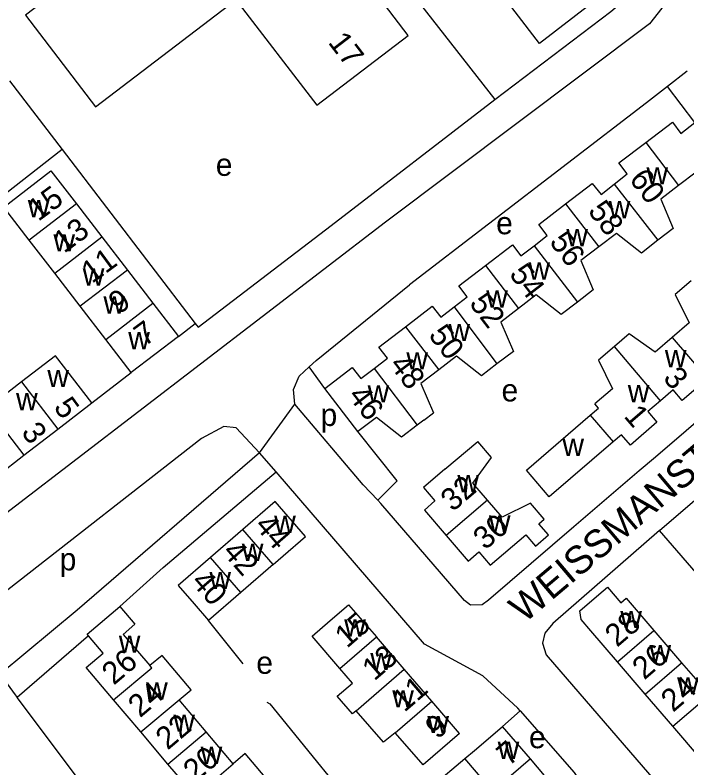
# Model space of a CAD drawing. Extents: x 158848 to 160613, y 385889 to 387762.
# Drawn here: x 160005.9 to 160125.8, y 386527.7 to 386662.2 of the extents above; entities that cross this region are included whole.
import ezdxf

# ---------------------------------------------------------------- set-up
doc = ezdxf.new("R2010")
doc.units = 0
for name, color, linetype in [('BLT_Basislijn', 7, 'Continuous'), ('BLT_Bebouwing', 7, 'Continuous'), ('BLT_Centroide', 7, 'Continuous'), ('BLT_Huisnummer', 7, 'Continuous'), ('BLT_Huisnummer_ tussenligend', 7, 'Continuous'), ('BLT_Onderverdeling_panden', 7, 'Continuous'), ('BLT_Straatnaam', 7, 'Continuous'), ('BLT_Vlakafsluiter', 7, 'Continuous')]:
    doc.layers.add(name, color=color, linetype=linetype)

msp = doc.modelspace()

# ---------------------------------------------------------------- linework, layer by layer
at = {"layer": 'BLT_Basislijn'}
for p, q in [((160125.84, 386652.14), (160122.33, 386649.41)), ((160004.85, 386650.41), (160014.24, 386638.14)), ((160127.21, 386642.98), (160122.33, 386649.41)), ((160062.28, 386624.59), (160091.49, 386647.08)), ((160014.24, 386638.14), (160038.02, 386607.09)), ((160035.02, 386604.77), (160038.02, 386607.09)), ((160019.55, 386592.89), (160026.6, 386598.34)), ((160061.18, 386595.45), (160058.37, 386599.34)), ((160000.42, 386578.15), (160007.45, 386583.53)), ((160052.45, 386580.6), (160049.48, 386583.96)), ((160117.29, 386580.74), (160105.63, 386570.74)), ((160156.76, 386528.66), (160120.89, 386570.12)), ((160024.56, 386556.5), (160032.3, 386563.48)), ((160046.58, 386546.31), (160040.39, 386554.01)), ((160018.99, 386551.28), (160006.23, 386540.3)), ((160018.93, 386523.43), (160006.23, 386540.3)), ((160096.06, 386537.88), (160092.88, 386535.1)), ((160070.18, 386515.95), (160086.18, 386529.36))]:
    msp.add_line(p, q, dxfattribs=at)
for points in [[(160037.07, 386716.89), (160066.71, 386678.86), (160091.49, 386647.08)], [(160091.49, 386647.08), (160112.23, 386662.8), (160114.67, 386664.97), (160111.18, 386670.16)], [(160121.03, 386668), (160121.35, 386667.04), (160121.3, 386663.42), (160119.12, 386660.61), (160072, 386625.2)], [(160122.33, 386649.41), (160118.57, 386646.49), (160076.28, 386613.96)], [(160014.24, 386638.14), (159973.45, 386606.21)], [(160072, 386625.2), (159994.85, 386566.02), (159992.27, 386564.83), (159988.99, 386564.97), (159986.32, 386567.3)], [(160038.02, 386607.09), (160038.55, 386606.41), (160062.28, 386624.59)], [(160058.37, 386599.34), (160059.6, 386600.47), (160076.28, 386613.96)], [(160153.03, 386611.43), (160120.17, 386583.21), (160117.29, 386580.74)], [(160055.81, 386592.66), (160055.54, 386595.28), (160056.56, 386597.68), (160058.37, 386599.34)], [(160070.62, 386575.53), (160068.02, 386578.28), (160055.81, 386592.66)], [(160049.48, 386583.96), (160045.31, 386588.46), (160043.15, 386588.7), (160039.17, 386586.55), (160004.57, 386559.51), (159997.74, 386553.78), (159997.8, 386551.51), (160003.17, 386544.41)], [(160070.62, 386575.53), (160074.05, 386578.99), (160067.05, 386587.78)], [(160120.89, 386570.12), (160138.05, 386584.8), (160139.23, 386585.32), (160141.71, 386585.23), (160143.94, 386583.68), (160176.56, 386545.83)], [(160049.48, 386583.96), (160016.93, 386555.88), (160003.17, 386544.41)], [(160032.3, 386563.48), (160052.45, 386580.6)], [(160096.06, 386537.88), (160095.64, 386538.36), (160089.38, 386544.17), (160078.95, 386549.8), (160052.45, 386580.6)], [(160105.63, 386570.74), (160090.41, 386557.64), (160089.25, 386556.84), (160087.15, 386556.77), (160086.07, 386557.61), (160071.18, 386574.93), (160070.62, 386575.53)], [(160120.89, 386570.12), (160101.88, 386553.46), (160100.45, 386551.77), (160100.03, 386549.96), (160100.67, 386547.91), (160133.83, 386509.51)], [(160003.17, 386544.41), (160005.89, 386540.76), (160006.23, 386540.3)], [(160050.78, 386539.46), (160051.37, 386539.12), (160070.18, 386515.95)], [(160096.06, 386537.88), (160105.65, 386526.85), (160106.06, 386526.36)]]:
    msp.add_lwpolyline(points, dxfattribs=at)
at = {"layer": 'BLT_Bebouwing'}
for p, q in [((160016.82, 386628.44), (160021.37, 386622.53)), ((160021.37, 386622.53), (160025.92, 386616.61)), ((160012.95, 386616.05), (160008.4, 386621.97)), ((160017.51, 386610.14), (160012.95, 386616.05)), ((160025.92, 386616.61), (160030.47, 386610.69)), ((160022.06, 386604.23), (160017.51, 386610.14)), ((160067.05, 386587.78), (160061.18, 386595.45)), ((160078.82, 386589.81), (160080.54, 386591.14)), ((160078.82, 386589.81), (160077.63, 386588.9)), ((160082.58, 386581.03), (160088.46, 386586)), ((160046.52, 386570.3), (160040.74, 386565.29)), ((160040.74, 386565.29), (160034.96, 386560.28)), ((160051.96, 386564.02), (160046.18, 386559.01)), ((160046.18, 386559.01), (160040.39, 386554.01)), ((160075.31, 386545.34), (160070.36, 386551.09)), ((160119.92, 386552.24), (160124.86, 386546.48)), ((160118.33, 386540.88), (160113.39, 386546.64)), ((160124.86, 386546.48), (160129.79, 386540.73)), ((160080.26, 386539.59), (160075.31, 386545.34)), ((160123.27, 386535.13), (160118.33, 386540.88)), ((160028.29, 386534.14), (160023.42, 386539.88)), ((160039.95, 386534.15), (160035.13, 386539.83)), ((160085.2, 386533.84), (160080.26, 386539.59)), ((160097.86, 386529.29), (160092.88, 386535.1)), ((160128.21, 386529.38), (160123.27, 386535.13)), ((160033.16, 386528.39), (160028.29, 386534.14)), ((160044.82, 386528.4), (160039.95, 386534.15)), ((160086.18, 386529.36), (160087.89, 386530.83)), ((160038.03, 386522.65), (160033.16, 386528.39)), ((160091.15, 386523.55), (160086.18, 386529.36)), ((160102.84, 386523.47), (160097.86, 386529.29))]:
    msp.add_line(p, q, dxfattribs=at)
msp.add_lwpolyline([(160039.46, 386707.71), (160023, 386695.11), (160033.29, 386681.66), (160007.73, 386662.12), (160020.21, 386645.77), (160045.27, 386664.94), (160059.74, 386646.07), (160076.07, 386658.53), (160059.12, 386680.71), (160058.39, 386680.18), (160051.48, 386689.22), (160052.83, 386690.21)], close=True, dxfattribs=at)
for points in [[(160096.96, 386679.71), (160108.81, 386664.29), (160099.47, 386657.11), (160087.64, 386672.57)], [(160118.45, 386639.4), (160123.23, 386643.05), (160124.74, 386640.99), (160127.21, 386642.98)], [(160112.82, 386631.95), (160115.16, 386633.78), (160113.68, 386635.74), (160118.45, 386639.4)], [(160008.4, 386621.97), (160003.86, 386627.86), (160012.27, 386634.36), (160016.82, 386628.44)], [(160134.93, 386632.93), (160131.93, 386630.62), (160127.48, 386634.13), (160124.33, 386631.72)], [(160104.15, 386628.44), (160108.92, 386632.1), (160110.47, 386630.11), (160112.82, 386631.95)], [(160124.33, 386631.72), (160121.15, 386629.27), (160123.37, 386624.04), (160120.64, 386621.94)], [(160098.51, 386620.96), (160100.88, 386622.78), (160099.39, 386624.78), (160104.15, 386628.44)], [(160120.64, 386621.94), (160117.67, 386619.66), (160113.21, 386623.17), (160110.06, 386620.75)], [(160089.87, 386617.46), (160094.65, 386621.11), (160096.14, 386619.13), (160098.51, 386620.96)], [(160110.06, 386620.75), (160106.87, 386618.3), (160109.09, 386613.07), (160106.26, 386610.9)], [(160084.23, 386610.02), (160086.58, 386611.83), (160085.08, 386613.8), (160089.87, 386617.46)], [(160126.54, 386614.69), (160123.71, 386612.25), (160126.23, 386607.17), (160123.18, 386604.56)], [(160106.26, 386610.9), (160103.38, 386608.68), (160098.92, 386612.19), (160095.75, 386609.76)], [(160030.47, 386610.69), (160035.02, 386604.77)], [(160075.58, 386606.49), (160080.34, 386610.15), (160081.88, 386608.21), (160084.23, 386610.02)], [(160095.75, 386609.76), (160092.58, 386607.32), (160094.82, 386602.1), (160091.89, 386599.85)], [(160069.95, 386599.05), (160072.33, 386600.85), (160070.82, 386602.84), (160075.58, 386606.49)], [(160035.02, 386604.77), (160026.6, 386598.34)], [(160123.18, 386604.56), (160120.14, 386601.95), (160115.49, 386605.21), (160112.85, 386602.94)], [(160026.6, 386598.34), (160022.06, 386604.23)], [(160112.85, 386602.94), (160110.04, 386600.53), (160112.55, 386595.43), (160109.39, 386592.71)], [(160019.55, 386592.89), (160013.05, 386601.32), (160007, 386596.63)], [(160091.89, 386599.85), (160089.11, 386597.72), (160084.65, 386601.23), (160081.49, 386598.8)], [(160061.18, 386595.45), (160066.06, 386599.2), (160067.57, 386597.25), (160069.95, 386599.05)], [(160081.49, 386598.8), (160078.3, 386596.35), (160080.54, 386591.14)], [(160129.49, 386597.2), (160124.98, 386593.32), (160123.38, 386595.22), (160121.11, 386593.27)], [(160007, 386596.63), (160000.95, 386591.95), (160007.45, 386583.53)], [(160013.5, 386588.21), (160019.55, 386592.89)], [(160108.55, 386590.67), (160110.05, 386591.96), (160109.39, 386592.71)], [(160121.11, 386593.27), (160118.84, 386591.33), (160120.43, 386589.42), (160115.72, 386585.36), (160114.13, 386587.21), (160112.63, 386585.92)], [(160077.63, 386588.9), (160074.85, 386586.76), (160070.39, 386590.27), (160067.05, 386587.78)], [(160101.24, 386576.14), (160097.16, 386580.89), (160108.55, 386590.67)], [(160007.45, 386583.53), (160013.5, 386588.21)], [(160090.19, 386575.53), (160087.59, 386578.57), (160090.89, 386583.12), (160088.46, 386586)], [(160112.63, 386585.92), (160101.24, 386576.14)], [(160082.58, 386581.03), (160078.76, 386577.8), (160080.81, 386575.38), (160078.95, 386573.75), (160082.83, 386569.22)], [(160051.96, 386564.02), (160053.74, 386565.56), (160057.73, 386569.03), (160052.3, 386575.3), (160046.52, 386570.3)], [(160082.83, 386569.22), (160086.76, 386564.63), (160088.66, 386566.26), (160090.69, 386563.89), (160097.04, 386569.33), (160098.76, 386567.32), (160101.07, 386569.3), (160099.36, 386571.31), (160100.34, 386572.15), (160097.89, 386575.01), (160092.8, 386572.49), (160090.19, 386575.53)], [(160034.96, 386560.28), (160037.82, 386556.98), (160040.39, 386554.01)], [(160113.39, 386546.64), (160108.65, 386552.16), (160106.94, 386554.22), (160106.66, 386555.73), (160110.08, 386558.67), (160111.61, 386559.98), (160114.02, 386557.17), (160114.98, 386557.99), (160119.92, 386552.24)], [(160018.99, 386551.28), (160018.74, 386551.57), (160024.56, 386556.5)], [(160024.56, 386556.5), (160027.22, 386553.37), (160025.18, 386551.54), (160029.94, 386545.96)], [(160063.84, 386545.48), (160058.89, 386551.23), (160062.12, 386554.01), (160065.41, 386556.84), (160070.36, 386551.09)], [(160023.42, 386539.88), (160018.55, 386545.62), (160021.6, 386548.2), (160018.99, 386551.28)], [(160035.13, 386539.83), (160037.3, 386541.67), (160032.11, 386547.8), (160029.94, 386545.96)], [(160066.74, 386537.9), (160066.1, 386537.35), (160063.39, 386540.5), (160066.11, 386542.84), (160063.84, 386545.48)], [(160073.74, 386533.98), (160071.65, 386532.28), (160066.74, 386537.9)], [(160087.89, 386530.83), (160089.48, 386532.2), (160092.88, 386535.1)], [(160085.2, 386533.84), (160078.69, 386528.23), (160075.43, 386532.02), (160073.74, 386533.98)], [(160051.83, 386524.52), (160046.94, 386530.29), (160044.82, 386528.4)]]:
    msp.add_lwpolyline(points, dxfattribs=at)
at = {"layer": 'BLT_Onderverdeling_panden'}
for p, q in [((160118.45, 386639.4), (160124.33, 386631.72)), ((160112.82, 386631.95), (160120.64, 386621.94)), ((160016.82, 386628.44), (160008.4, 386621.97)), ((160104.15, 386628.44), (160110.06, 386620.75)), ((160012.95, 386616.05), (160021.37, 386622.53)), ((160098.51, 386620.96), (160106.26, 386610.9)), ((160089.87, 386617.46), (160095.75, 386609.76)), ((160025.92, 386616.61), (160017.51, 386610.14)), ((160022.06, 386604.23), (160030.47, 386610.69)), ((160084.23, 386610.02), (160091.89, 386599.85)), ((160075.58, 386606.49), (160081.49, 386598.8)), ((160123.18, 386604.56), (160129.49, 386597.2)), ((160121.11, 386593.27), (160112.85, 386602.94)), ((160069.95, 386599.05), (160077.63, 386588.9)), ((160007, 386596.63), (160013.5, 386588.21)), ((160090.19, 386575.53), (160082.83, 386569.22)), ((160051.96, 386564.02), (160046.52, 386570.3)), ((160046.18, 386559.01), (160040.74, 386565.29)), ((160063.84, 386545.48), (160070.36, 386551.09)), ((160113.39, 386546.64), (160119.92, 386552.24)), ((160118.33, 386540.88), (160124.86, 386546.48)), ((160066.74, 386537.9), (160075.31, 386545.34)), ((160123.27, 386535.13), (160129.79, 386540.73)), ((160028.29, 386534.14), (160035.13, 386539.83)), ((160073.74, 386533.98), (160080.26, 386539.59)), ((160033.16, 386528.39), (160039.95, 386534.15)), ((160038.03, 386522.65), (160044.82, 386528.4)), ((160097.86, 386529.29), (160091.15, 386523.55))]:
    msp.add_line(p, q, dxfattribs=at)
for points in [[(160108.55, 386590.67), (160112.63, 386585.92)], [(160023.42, 386539.88), (160030.29, 386545.55), (160029.94, 386545.96)]]:
    msp.add_lwpolyline(points, dxfattribs=at)
at = {"layer": 'BLT_Vlakafsluiter'}
msp.add_line((160049.48, 386583.96), (160055.81, 386592.66), dxfattribs=at)

# ---------------------------------------------------------------- texts
at = {"layer": 'BLT_Centroide'}
for s, p in [('e', (160041.7, 386633.44)), ('w', (160118.58, 386631.92)), ('w', (160008.14, 386626.05)), ('w', (160111.84, 386625.88)), ('e', (160091.75, 386623.01)), ('w', (160104.28, 386620.88)), ('w', (160012.71, 386619.95)), ('w', (160017.94, 386613.85)), ('w', (160097.5, 386614.91)), ('w', (160089.98, 386609.92)), ('w', (160021.64, 386608.84)), ('w', (160083.23, 386603.94)), ('w', (160026.06, 386602.46)), ('w', (160121.87, 386599.25)), ('w', (160075.72, 386598.86)), ('w', (160011.62, 386595.71)), ('w', (160068.8, 386592.97)), ('e', (160092.71, 386593.15)), ('w', (160115.25, 386593.02)), ('w', (160006.04, 386591.57)), ('p', (160060.4, 386588.77)), ('w', (160103.57, 386583.41)), ('w', (160084.83, 386576.94)), ('w', (160052.12, 386569.66)), ('w', (160090.45, 386569.72)), ('w', (160046.34, 386564.66)), ('p', (160013.82, 386562.98)), ('w', (160040.56, 386559.64)), ('w', (160113.91, 386552.66)), ('w', (160064.62, 386551.16)), ('w', (160024.38, 386548.27)), ('w', (160119.12, 386546.56)), ('e', (160048.93, 386544.5)), ('w', (160069.28, 386545.16)), ('w', (160029.25, 386539.88)), ('w', (160124.06, 386540.81)), ('w', (160073.2, 386538.5)), ('w', (160034.12, 386534.16)), ('w', (160079.47, 386533.91)), ('e', (160097.61, 386531.21)), ('w', (160092.02, 386529.31)), ('w', (160038.99, 386528.41))]:
    msp.add_text(s, height=4, dxfattribs=at).set_placement(p)
at = {"layer": 'BLT_Huisnummer'}
for s, rotation, p in [('17', 307.4311, (160061.62, 386657.26)), ('15', 36.2399, (160010, 386625.21)), ('58', 307.4311, (160108, 386627.13)), ('11', 36.2399, (160019.6, 386614.12)), ('54', 307.4311, (160093.95, 386615.84)), ('7', 36.2399, (160028.98, 386602.86)), ('50', 307.4311, (160079.54, 386604.96)), ('5', 306.2399, (160012.62, 386592.09)), ('46', 307.4311, (160065.17, 386594.13)), ('1', 310.7404, (160114.41, 386590.45)), ('3', 306.2399, (160006.84, 386587.61)), ('32', 40.6135, (160084, 386573.33)), ('30', 40.5871, (160089.8, 386566.49)), ('44', 310.9113, (160048.47, 386570.89)), ('40', 310.9203, (160037.15, 386560.85)), ('15', 40.7039, (160065.11, 386548.96)), ('28', 40.6381, (160113.33, 386549.14)), ('26', 40.2776, (160023.48, 386542.36)), ('9', 40.7133, (160081.26, 386532.69)), ('7', 40.5773, (160093.98, 386527.87)), ('20', 40.2776, (160038.01, 386524.99))]:
    msp.add_text(s, height=4, rotation=rotation, dxfattribs=at).set_placement(p)
at = {"layer": 'BLT_Huisnummer_ tussenligend'}
for s, rotation, p in [('60', 307.4311, (160115.37, 386632.81)), ('13', 36.2399, (160014.61, 386619.52)), ('56', 307.4311, (160101.12, 386621.61)), ('9', 36.2399, (160024.42, 386608.59)), ('52', 307.4311, (160086.82, 386610.62)), ('48', 307.4311, (160072.55, 386599.69)), ('3', 310.7404, (160121.39, 386597.22)), ('42', 310.9203, (160042.72, 386566.18)), ('26', 40.6381, (160118.2, 386543.3)), ('13', 40.7133, (160069.99, 386543.11)), ('24', 40.2776, (160028.17, 386536.54)), ('11', 40.7133, (160075.36, 386537.52)), ('24', 40.6381, (160123.33, 386537.52)), ('22', 40.2776, (160033.1, 386530.77))]:
    msp.add_text(s, height=4, rotation=rotation, dxfattribs=at).set_placement(p)
at = {"layer": 'BLT_Straatnaam'}
msp.add_text('WEISSMANSTRAAT', height=4.9999, rotation=40.2276, dxfattribs=at).set_placement((160096.78, 386553.42))

doc.saveas('drawing.dxf')
